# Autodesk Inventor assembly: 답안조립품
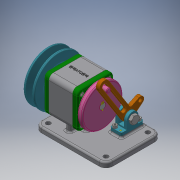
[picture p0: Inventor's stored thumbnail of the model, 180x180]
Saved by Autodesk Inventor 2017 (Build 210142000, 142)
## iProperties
Part Number: 답안조립품
Material: 일반
Document SubType Name: Assembly
Designer: 7-1
Mass: 1532.4 g
Surface Area: 1486.39 cm^2
Volume: 469.454 cm^3
Density: 3.26422 g/cm^3
Author: 7-1
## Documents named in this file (19)
- C:\Users\7-1\Desktop\601106V1038\답안조립품.iam
- C:\Users\7-1\Desktop\601106V1038\본체.ipt
- C:\Users\7-1\Desktop\601106V1038\V-벨트풀리.ipt
- C:\Users\7-1\Desktop\601106V1038\너트 M8.ipt
- C:\Users\7-1\Desktop\601106V1038\너트 M10x1.ipt
- C:\Users\7-1\Desktop\601106V1038\돌림판.ipt
- C:\Users\7-1\Desktop\601106V1038\멈춤나사 M3x5.ipt
- C:\Users\7-1\Desktop\601106V1038\베어링 6004.ipt
- C:\Users\7-1\Desktop\601106V1038\볼트 M4.ipt
- C:\Users\7-1\Desktop\601106V1038\오일 실 17 30 5.ipt
- C:\Users\7-1\Desktop\601106V1038\와셔 8x15.5.ipt
- C:\Users\7-1\Desktop\601106V1038\축.ipt
- C:\Users\7-1\Desktop\601106V1038\커버.ipt
- C:\Users\7-1\Desktop\601106V1038\크랭크.ipt
- C:\Users\7-1\Desktop\601106V1038\키 4 x 4 x 8.ipt
- C:\Users\7-1\Desktop\601106V1038\키 5 x 5 x 12.ipt
- C:\Users\7-1\Desktop\601106V1038\핀 3 x 8.ipt
- C:\Users\7-1\Desktop\601106V1038\힌지 축.ipt
- C:\Users\7-1\Desktop\601106V1038\힌지.ipt
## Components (3 placed, 2 different names)
1. V-벨트풀리:1
2. 핀 3 x 8:1 — 플러쉬:2
3. 핀 3 x 8:2 — 플러쉬:1
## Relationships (2: Flush 2)
- 플러쉬:1 [Flush]: 핀 3 x 8:2
- 플러쉬:2 [Flush]: 핀 3 x 8:1
